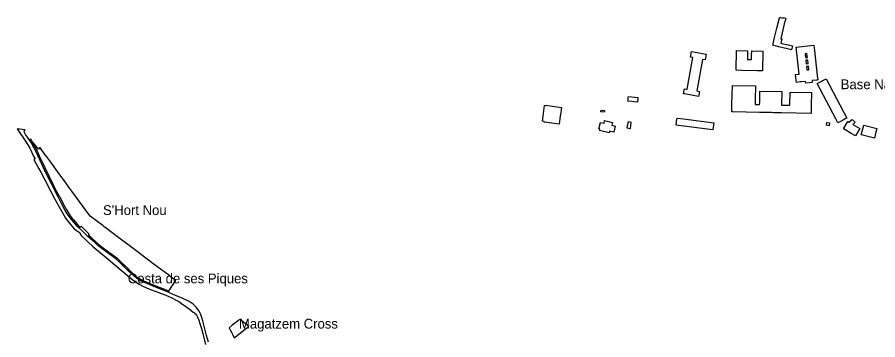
# Model space of a CAD drawing. Extents: x 599451 to 612034, y 4411179 to 4428219.
# Drawn here: x 607460 to 608515, y 4416524 to 4416919 of the extents above; entities that cross this region are included whole.
import ezdxf

# ---------------------------------------------------------------- set-up
doc = ezdxf.new("R2010")
doc.units = 0
doc.layers.add('Elements patrimonials', color=7, linetype='Continuous')

msp = doc.modelspace()

# ---------------------------------------------------------------- linework, layer by layer
at = {"layer": 'Elements patrimonials'}
for points in [[(608393.8, 4416916.7), (608394, 4416917), (608394.8, 4416919.2), (608395.3, 4416919), (608398.8, 4416918.1), (608398.9, 4416918.7), (608401.9, 4416917.9), (608401.1, 4416914.9), (608400.9, 4416914.2), (608398.4, 4416903.8), (608395.7, 4416892.9), (608397.1, 4416892.6), (608396.3, 4416889.2), (608395.9, 4416887.5), (608400.9, 4416886.3), (608405, 4416885.3), (608405.3, 4416885.2), (608410.2, 4416884.3), (608409, 4416879.3), (608404.1, 4416880.3), (608393.5, 4416883), (608393.2, 4416883), (608385.9, 4416884.8), (608386.3, 4416886.5), (608387.9, 4416892.7), (608391.1, 4416905.8)], [(608434.1, 4416841.6), (608434.4, 4416839.2), (608426.6, 4416838.3), (608426.3, 4416840.7), (608420.9, 4416840.1), (608419.7, 4416840), (608415, 4416839.5), (608414, 4416849), (608418.3, 4416849.5), (608414.6, 4416882.7), (608422.2, 4416883.5), (608429.1, 4416884.3), (608436.5, 4416885.1), (608436.5, 4416884.9), (608437.2, 4416878.3), (608440.6, 4416847.9), (608441.2, 4416842.4), (608440.6, 4416842.3), (608439.6, 4416842.2)], [(608281.1, 4416831.1), (608288.2, 4416869.7), (608285, 4416870.3), (608286.2, 4416877.2), (608304.5, 4416873.8), (608303.3, 4416866.9), (608299.9, 4416867.5), (608292.8, 4416828.9), (608296.2, 4416828.3), (608295, 4416822.1), (608277.9, 4416825.3), (608276.6, 4416825.5), (608277.7, 4416831.7), (608279.7, 4416831.3)], [(608348, 4416854.1), (608341.2, 4416854.2), (608341.7, 4416878.3), (608355.2, 4416878.1), (608355.2, 4416877.3), (608355.1, 4416875.2), (608355.1, 4416873), (608355, 4416867.4), (608355, 4416867.3), (608355.8, 4416867.4), (608360, 4416867.3), (608360.1, 4416872.9), (608360.2, 4416878), (608373.9, 4416877.7), (608373.4, 4416853.6), (608366.7, 4416853.7)], [(608428.4, 4416870), (608427.9, 4416874.7), (608425.5, 4416874.4), (608426, 4416869.7)], [(608429.2, 4416862.5), (608428.8, 4416866.7), (608426.4, 4416866.5), (608426.9, 4416862.2)], [(608427.7, 4416854.6), (608430.1, 4416854.8), (608429.6, 4416859.3), (608427.2, 4416859)], [(608463.4, 4416794.7), (608440.6, 4416838.1), (608442, 4416838.8), (608450.8, 4416843.5), (608451.3, 4416843.7), (608476.6, 4416795.7), (608474.8, 4416794.7), (608471.3, 4416792.8), (608465.9, 4416790)], [(608337.2, 4416803.2), (608335.7, 4416803.2), (608335.9, 4416811.7), (608335.9, 4416812.7), (608335.9, 4416812.9), (608336.5, 4416835.6), (608364.7, 4416835.1), (608364.5, 4416819.1), (608364.4, 4416814.2), (608364.3, 4416812.4), (608369.9, 4416812.3), (608370, 4416815.3), (608370, 4416819.6), (608370.2, 4416828.7), (608397.1, 4416828.2), (608396.8, 4416811.7), (608407, 4416811.6), (608407.3, 4416827.6), (608433.4, 4416827.2), (608433.1, 4416811.1), (608433, 4416801.5), (608396.6, 4416802.2), (608396, 4416802.2), (608394.8, 4416802.2), (608393.4, 4416802.2), (608389.4, 4416802.3), (608387.9, 4416802.3), (608387.1, 4416802.3), (608384.4, 4416802.4), (608384, 4416802.4), (608382.4, 4416802.4), (608378.5, 4416802.5), (608376.9, 4416802.5), (608376.1, 4416802.5), (608373.7, 4416802.6), (608373, 4416802.6), (608371.5, 4416802.6), (608370.4, 4416802.6), (608369.7, 4416802.6)], [(608213.3, 4416816), (608208.4, 4416816.5), (608208.6, 4416818.8), (608208.8, 4416820.3), (608208.9, 4416821.1), (608208.9, 4416821.4), (608209, 4416822.1), (608209, 4416822.2), (608220.8, 4416821.1), (608220.7, 4416820.2), (608220.6, 4416818.9), (608220.5, 4416818.4), (608220.5, 4416817.6), (608220.4, 4416816.9), (608220.2, 4416815.4), (608215.4, 4416815.8)], [(608105.9, 4416791.7), (608103.8, 4416792), (608104.1, 4416794.7), (608106.2, 4416811), (608106.8, 4416811), (608106.9, 4416811), (608107.2, 4416811), (608107.3, 4416811.1), (608107.4, 4416811.2), (608107.4, 4416811.2), (608107.4, 4416811.3), (608107.5, 4416811.3), (608107.5, 4416811.3), (608107.5, 4416811.4), (608107.5, 4416811.4), (608107.5, 4416811.4), (608107.6, 4416811.5), (608113.2, 4416810.7), (608127.1, 4416808.8), (608125.8, 4416799.9), (608125.6, 4416798.4), (608125.1, 4416794.7), (608124.2, 4416788.4), (608121.3, 4416788.7), (608105.8, 4416790.8), (608105.9, 4416791.5)], [(608179.6, 4416804.2), (608179.5, 4416803), (608175.3, 4416803.4), (608175.4, 4416804.6), (608175.5, 4416805.4), (608179.7, 4416805)], [(608186, 4416779.6), (608185.8, 4416778.7), (608185.6, 4416777.7), (608173.7, 4416780.5), (608173.8, 4416780.6), (608174.2, 4416782.3), (608173.3, 4416782.5), (608173, 4416782.5), (608174.9, 4416790.5), (608179.2, 4416789.5), (608179.9, 4416792.6), (608189.7, 4416790.3), (608188.9, 4416786.9), (608193, 4416786), (608191.3, 4416778.4), (608187.1, 4416779.3)], [(608211.1, 4416782.7), (608207.7, 4416783.4), (608207.7, 4416783.7), (608209, 4416791.4), (608212, 4416790.9)], [(608267.5, 4416787.1), (608268.5, 4416794.7), (608268.7, 4416795.7), (608276.7, 4416794.7), (608313.8, 4416789.9), (608312.7, 4416781.2), (608270.5, 4416786.7)], [(608452.1, 4416790.5), (608455.7, 4416790), (608455.3, 4416786.4), (608451.7, 4416786.9)], [(608477.4, 4416779.8), (608472.7, 4416782.5), (608477.9, 4416791.5), (608479.3, 4416790.7), (608482.1, 4416793.1), (608483.3, 4416794.1), (608486.9, 4416790.9), (608484.3, 4416787.7), (608492.5, 4416782.9), (608487.2, 4416774), (608482.2, 4416776.9), (608480.8, 4416777.8), (608478.9, 4416778.9)], [(608494.3, 4416775.4), (608497.4, 4416787.1), (608513.6, 4416782.9), (608513.5, 4416782.5), (608512.5, 4416779), (608510.5, 4416771.2), (608501, 4416773.7)], [(607487.8, 4416760), (607487.7, 4416759.9), (607486, 4416757.9), (607480.9, 4416764.2), (607480.1, 4416765.2), (607475.9, 4416770.2), (607478.6, 4416766), (607479.8, 4416764), (607481.6, 4416761), (607483.5, 4416757.2), (607484.4, 4416755.3), (607487.1, 4416749.6), (607491, 4416741.2), (607493.8, 4416735.3), (607498.9, 4416725.1), (607504.3, 4416714.2), (607508.4, 4416706), (607511.4, 4416700.1), (607511.7, 4416699.6), (607515, 4416693.5), (607515.6, 4416692.4), (607519.9, 4416684.4), (607524.9, 4416676.2), (607527.7, 4416672.5), (607529, 4416671.1), (607535.6, 4416663.6), (607537.1, 4416662.2), (607537.9, 4416662.8), (607538.4, 4416663.3), (607542.4, 4416659.4), (607544.6, 4416657.3), (607547.1, 4416655), (607548, 4416654.1), (607547.7, 4416653.8), (607547.1, 4416653.2), (607548.8, 4416651.4), (607549, 4416651.2), (607550.1, 4416650.1), (607551.8, 4416648.4), (607556.2, 4416644.5), (607560.2, 4416640.9), (607564.2, 4416637.9), (607567.4, 4416635.4), (607570.5, 4416633.2), (607576.1, 4416629.1), (607576.1, 4416629.1), (607579.3, 4416626.7), (607582.1, 4416624.6), (607583.5, 4416623.3), (607585.5, 4416621.5), (607586.8, 4416620.2), (607589.3, 4416617.8), (607591.9, 4416615.2), (607594.7, 4416612.3), (607596.9, 4416610.2), (607599.3, 4416607.9), (607602.1, 4416605.2), (607604.4, 4416603.2), (607607.6, 4416600.8), (607609.8, 4416599.5), (607611.9, 4416598.1), (607614.8, 4416596.7), (607616, 4416596.3), (607621.4, 4416594), (607623.1, 4416593.3), (607627, 4416591.7), (607633, 4416589.3), (607638.6, 4416587), (607643.5, 4416585), (607645.7, 4416584), (607649.1, 4416589.3), (607650.3, 4416590.9), (607654.6, 4416597.1), (607654.4, 4416597.1), (607650.5, 4416600), (607646.5, 4416603), (607642.9, 4416605.6), (607640.8, 4416607.2), (607637.3, 4416609.8), (607629.5, 4416615.4), (607616.1, 4416625.5), (607615.9, 4416625.7), (607608.6, 4416631.1), (607597.3, 4416639.7), (607584.5, 4416649.3), (607567.4, 4416662.2), (607567.2, 4416662.4), (607564.8, 4416664.2), (607549.3, 4416675.9), (607527.1, 4416706.3), (607523.5, 4416711.2), (607516.8, 4416720.4), (607514.9, 4416722.9), (607509.6, 4416730.3), (607501.1, 4416741.8), (607496.3, 4416748.4), (607493.3, 4416752.5), (607487.8, 4416760)], [(607732.9, 4416549.5), (607731.2, 4416548.1), (607723.5, 4416542.1), (607719.7, 4416539.2), (607721.4, 4416535.9), (607723, 4416532.9), (607724.2, 4416530.4), (607726.1, 4416526.7), (607739.5, 4416537.2), (607743.9, 4416540.7), (607733.4, 4416549.3)]]:
    msp.add_lwpolyline(points, close=True, dxfattribs=at)
msp.add_lwpolyline([(607694.5, 4416521.3), (607692.2, 4416529.8), (607687.4, 4416547.5), (607686.3, 4416551.8), (607684.8, 4416556.1), (607682.9, 4416559.6), (607679.4, 4416564.3), (607675.7, 4416567.9), (607670.7, 4416571.2), (607663, 4416574.8), (607653.4, 4416579), (607643.1, 4416583.3), (607629.7, 4416588.9), (607616.2, 4416594.4), (607610.5, 4416597.1), (607606.3, 4416599.9), (607602.4, 4416603.1), (607596.9, 4416608.1), (607590.9, 4416614.1), (607584.9, 4416619.9), (607580.7, 4416623.7), (607573.6, 4416628.9), (607565.4, 4416634.9), (607559, 4416640), (607555.5, 4416643), (607555.1, 4416643.4), (607546.7, 4416651), (607540.2, 4416657.3), (607534.1, 4416663.2), (607529.3, 4416668.4), (607524.9, 4416673.7), (607521.4, 4416678.7), (607519, 4416682.8), (607515.2, 4416689.7), (607510.5, 4416698.5), (607506.4, 4416706.4), (607501.9, 4416715.5), (607497.3, 4416724.8), (607492.3, 4416734.8), (607488.2, 4416743.7), (607485.2, 4416750), (607484.2, 4416752.2), (607480.9, 4416758.8), (607477, 4416765.8), (607472.7, 4416772.3), (607470.2, 4416775.8), (607469.9, 4416776.4), (607468.9, 4416778.1), (607468.7, 4416779.9), (607469.7, 4416781.2), (607460.1, 4416782.7), (607470.1, 4416767.4), (607474.3, 4416761), (607475.5, 4416758.9), (607480.2, 4416749.3), (607481.9, 4416745.9), (607480.3, 4416744.9), (607486.1, 4416734.6), (607489, 4416729.5), (607494, 4416720.2), (607500.8, 4416706.8), (607506.2, 4416696.4), (607513, 4416684.3), (607519.3, 4416673.1), (607525.8, 4416665), (607530, 4416660.4), (607536.3, 4416655.6), (607538.5, 4416651.9), (607546.2, 4416644.8), (607553.3, 4416638.3), (607559.8, 4416632.7), (607569.1, 4416625.2), (607579.6, 4416616.3), (607589.8, 4416607.4), (607597.9, 4416600.7), (607603.9, 4416596.2), (607609.7, 4416592.6), (607615, 4416589.7), (607621.4, 4416586.9), (607635.5, 4416581.5), (607642.2, 4416579), (607649.6, 4416575.8), (607654, 4416573.4), (607658, 4416571.1), (607661.4, 4416568.7), (607671, 4416562.3), (607675.9, 4416558.4), (607677.2, 4416557.2), (607677.5, 4416556.9), (607678.4, 4416556), (607679.8, 4416554.4), (607681, 4416552), (607682.7, 4416548.3), (607684, 4416544.3), (607685.5, 4416539.4), (607687.4, 4416531.9), (607690.9, 4416518.6)], dxfattribs=at)

# ---------------------------------------------------------------- texts
for s, p in [('Base Naval', (608469.3, 4416831.1)), ("S'Hort Nou", (607565.2, 4416677.1)), ('Costa de ses Piques', (607595.6, 4416593.5)), ('Magatzem Cross', (607731.8, 4416538.1))]:
    msp.add_text(s, height=12, dxfattribs=at).set_placement(p)

doc.saveas('drawing.dxf')
